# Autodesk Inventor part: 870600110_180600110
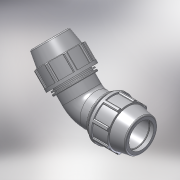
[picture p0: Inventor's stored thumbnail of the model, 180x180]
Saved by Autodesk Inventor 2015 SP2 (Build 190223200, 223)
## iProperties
Created: 2017-02
Part Number: 870600110_180600110
Material: PVC-Piping
Description: PLASSON 45° ELBOW 110-110
Document SubType Name: Modeling
Designer: KIM
Mass: 92.6774 g
Surface Area: 199.44 cm^2
Volume: 66.1981 cm^3
Density: 1.4 g/cm^3
Appearance: Smooth - White
Author: Кирилл
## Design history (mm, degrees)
derived "87060.ipt"
feature "Solid1::87060.ipt"
tag "TaggingFeature1"
body "Solid1"
other parameters: "d4" = 19.75, "d5" = 59.25, "d7" = 181, "d9" = 33.85714, "d11" = 7.9, "d13" = 120 deg, "d14" = 143, "d15" = 10 deg, "d16" = 157.47, "d18" = 5.5, "d19" = 35 deg, "d20" = 17.5 deg, "d21" = 168.33, "d23" = 0, "d25" = 360 deg, "d27" = 3.62, "d33" = 2.2, "d42" = 80.58, "d43" = 5.43, "d46" = 2.2, "d51" = 237, "d59" = 135 deg, "d63" = 196, "d64" = 99, "d67" = 135.75, "d68" = 14.22, "d70" = 45 deg, "d72" = 12.06667, "d73" = 0, "d75" = 135 deg, "d77" = 154.3206, "d78" = 4.74, "E_" = 181, "A_" = 237, "l_" = 196
